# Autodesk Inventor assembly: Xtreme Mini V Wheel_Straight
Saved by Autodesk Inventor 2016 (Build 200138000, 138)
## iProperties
Created: 2015-11
Part Number: Xtreme Mini V Wheel_Straight
Document SubType Name: Assembly
Designer: John
Author: John
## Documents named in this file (6)
- D:\3D Printer Designs\John Ledden Designs\DLP Printer\V0-4\Xtreme Mini V Wheel_Straight.iam
- D:\3D Printer Designs\John Ledden Designs\DLP Printer\V0-4\Xtreme Mini V Wheel.ipt
- D:\3D Printer Designs\John Ledden Designs\DLP Printer\V0-4\Ball Bearing 5 x 10 x 4.2.ipt
- D:\3D Printer Designs\John Ledden Designs\DLP Printer\V0-4\Precision Shim 8 x 5 x 1.ipt
- D:\3D Printer Designs\John Ledden Designs\DLP Printer\V0-4\Nylon Insert Lock Nut M5.ipt
- D:\3D Printer Designs\John Ledden Designs\DLP Printer\V0-4\Aluminum Spacer 6mm.ipt
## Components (7 placed, 7 different names)
1. Xtreme Mini V Wheel_1095
2. Ball Bearing 5 x 10 x 4.2_1096
3. Ball Bearing 5 x 10 x 4.2_1097
4. Precision Shim 8 x 5 x 1_1098
5. Precision Shim 8 x 5 x 1_1099
6. Nylon Insert Lock Nut M5_1100
7. Aluminum Spacer 6mm_1101
